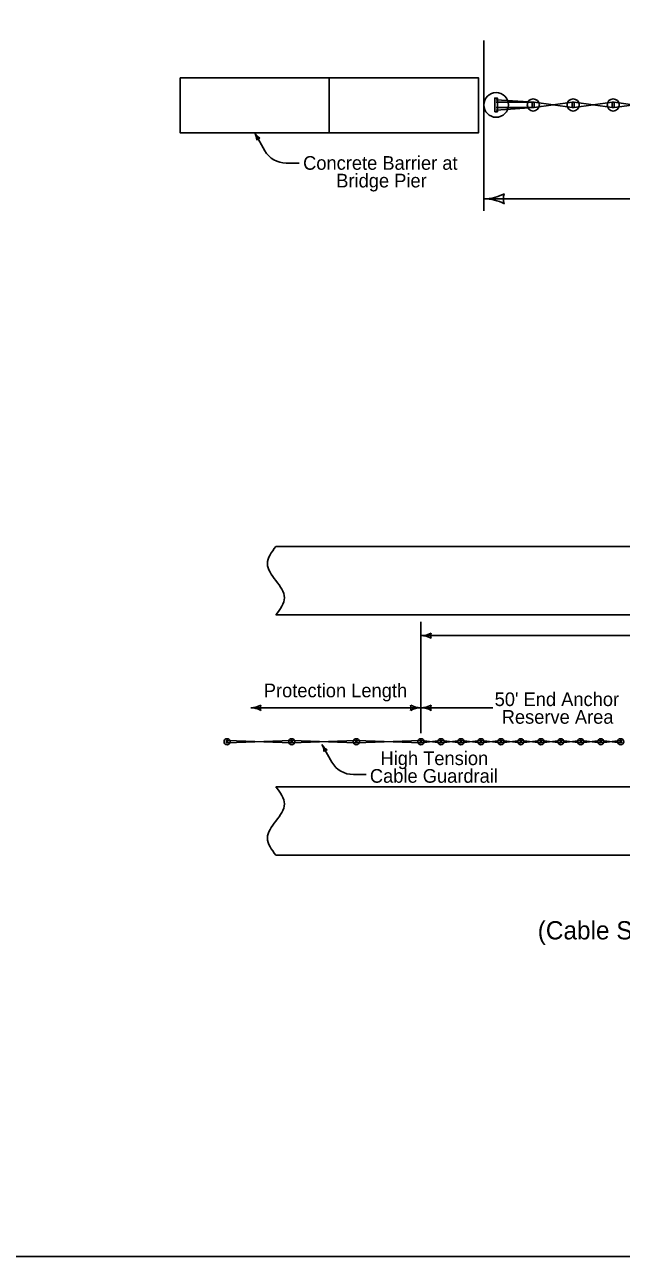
# Model space of a CAD drawing. Extents: x 10133 to 81668, y 7924 to 11018.
# Drawn here: x 22568 to 23092, y 7924 to 9005 of the extents above; entities that cross this region are included whole.
import ezdxf

# ---------------------------------------------------------------- set-up
doc = ezdxf.new("R2010")
doc.units = 0
for name, color, linetype in [('dsnCellElements', 7, 'Continuous'), ('DsnShtRevisedText', 7, 'Continuous'), ('dsnStdDimension', 7, 'Continuous'), ('Level 8', 7, 'Continuous'), ('SheetBorder', 7, 'Continuous')]:
    doc.layers.add(name, color=color, linetype=linetype)

msp = doc.modelspace()

# ---------------------------------------------------------------- linework, layer by layer
at = {"layer": 'dsnCellElements'}
for p, q in [((22981.8, 8939.2), (23015.3, 8936.9)), ((22981.8, 8936.9), (23013.5, 8936.9)), ((22981.8, 8932.4), (23013.5, 8932.4)), ((22981.8, 8930), (23015.3, 8932.4)), ((23015.3, 8936.9), (23048.5, 8932.4)), ((23015.3, 8932.4), (23048.5, 8936.9)), ((23050.4, 8936.9), (23083.6, 8932.4)), ((23050.4, 8932.4), (23083.6, 8936.9)), ((23085.5, 8936.9), (23118.7, 8932.4)), ((23085.5, 8932.4), (23118.7, 8936.9)), ((22801.9, 8376.8), (22746.1, 8374.6)), ((22801.9, 8374.6), (22746.1, 8376.8)), ((22858.6, 8376.8), (22802.9, 8374.6)), ((22858.6, 8374.6), (22802.9, 8376.8)), ((22915.3, 8376.8), (22859.6, 8374.6)), ((22915.3, 8374.6), (22859.6, 8376.8)), ((22932.9, 8376.8), (22916.3, 8374.6)), ((22932.9, 8374.6), (22916.3, 8376.8)), ((22950.4, 8376.8), (22933.8, 8374.6)), ((22950.4, 8374.6), (22933.8, 8376.8)), ((22968, 8376.8), (22951.3, 8374.6)), ((22968, 8374.6), (22951.3, 8376.8)), ((22985.5, 8376.8), (22968.9, 8374.6)), ((22985.5, 8374.6), (22968.9, 8376.8)), ((23003.1, 8376.8), (22986.4, 8374.6)), ((23003.1, 8374.6), (22986.4, 8376.8)), ((23020.6, 8376.8), (23004, 8374.6)), ((23020.6, 8374.6), (23004, 8376.8)), ((23038.2, 8376.8), (23021.5, 8374.6)), ((23038.2, 8374.6), (23021.5, 8376.8)), ((23055.7, 8374.6), (23039.1, 8376.8)), ((23055.7, 8376.8), (23039.1, 8374.6)), ((23073.2, 8376.8), (23056.6, 8374.6)), ((23073.2, 8374.6), (23056.6, 8376.8)), ((23090.8, 8376.8), (23074.2, 8374.6)), ((23090.8, 8374.6), (23074.2, 8376.8))]:
    msp.add_line(p, q, dxfattribs=at)
for points in [[(22980.6, 8928.6), (22980.6, 8940.6), (22983, 8940.6), (22983, 8928.6)], [(23013.5, 8932.4), (23013.5, 8936.9), (23015.3, 8936.9), (23015.3, 8932.4)], [(23048.5, 8932.4), (23048.5, 8936.9), (23050.4, 8936.9), (23050.4, 8932.4)], [(23083.7, 8932.4), (23083.7, 8936.9), (23085.5, 8936.9), (23085.5, 8932.4)], [(22746.1, 8374.6), (22746.1, 8376.8), (22745.2, 8376.8), (22745.2, 8374.6)], [(22802.9, 8374.6), (22802.9, 8376.8), (22801.9, 8376.8), (22801.9, 8374.6)], [(22802.9, 8374.6), (22802.9, 8376.8), (22801.9, 8376.8), (22801.9, 8374.6)], [(22859.6, 8374.6), (22859.6, 8376.8), (22858.6, 8376.8), (22858.6, 8374.6)], [(22859.6, 8374.6), (22859.6, 8376.8), (22858.6, 8376.8), (22858.6, 8374.6)], [(22916.3, 8374.6), (22916.3, 8376.8), (22915.3, 8376.8), (22915.3, 8374.6)], [(22916.3, 8374.6), (22916.3, 8376.8), (22915.3, 8376.8), (22915.3, 8374.6)], [(22933.8, 8374.6), (22933.8, 8376.8), (22932.9, 8376.8), (22932.9, 8374.6)], [(22951.3, 8374.6), (22951.3, 8376.8), (22950.4, 8376.8), (22950.4, 8374.6)], [(22968.9, 8374.6), (22968.9, 8376.8), (22968, 8376.8), (22968, 8374.6)], [(22986.4, 8374.6), (22986.4, 8376.8), (22985.5, 8376.8), (22985.5, 8374.6)], [(23004, 8374.6), (23004, 8376.8), (23003.1, 8376.8), (23003.1, 8374.6)], [(23021.5, 8374.6), (23021.5, 8376.8), (23020.6, 8376.8), (23020.6, 8374.6)], [(23039.1, 8374.6), (23039.1, 8376.8), (23038.2, 8376.8), (23038.2, 8374.6)], [(23056.6, 8374.6), (23056.6, 8376.8), (23055.7, 8376.8), (23055.7, 8374.6)], [(23074.2, 8374.6), (23074.2, 8376.8), (23073.2, 8376.8), (23073.2, 8374.6)], [(23091.7, 8374.6), (23091.7, 8376.8), (23090.8, 8376.8), (23090.8, 8374.6)]]:
    msp.add_lwpolyline(points, close=True, dxfattribs=at)
for centre, radius in [((22981.8, 8934.6), 10.8), ((23014.4, 8934.6), 5.32), ((23049.4, 8934.6), 5.32), ((23084.6, 8934.6), 5.32), ((22745.7, 8375.7), 2.66), ((22802.4, 8375.7), 2.66), ((22802.4, 8375.7), 2.66), ((22859.1, 8375.7), 2.66), ((22859.1, 8375.7), 2.66), ((22915.8, 8375.7), 2.66), ((22915.8, 8375.7), 2.66), ((22933.4, 8375.7), 2.66), ((22950.9, 8375.7), 2.66), ((22968.4, 8375.7), 2.66), ((22986, 8375.7), 2.66), ((23003.5, 8375.7), 2.66), ((23021.1, 8375.7), 2.66), ((23038.6, 8375.7), 2.66), ((23056.1, 8375.7), 2.66), ((23073.7, 8375.7), 2.66), ((23091.2, 8375.7), 2.66)]:
    msp.add_circle(centre, radius, dxfattribs=at)
at = {"layer": 'DsnShtRevisedText'}
for p, q in [((22971, 8841.7), (22971, 8991.2)), ((22778.8, 8894.4), (22769.9, 8910)), ((22797.6, 8883.6), (22808.8, 8883.6)), ((22971, 8852.2), (23201.1, 8852.2)), ((22915.8, 8383.2), (22915.8, 8480.8)), ((23207.3, 8468.8), (22915.8, 8468.8)), ((22892.8, 8405.5), (22766.4, 8405.5)), ((22915.8, 8405.5), (22892.8, 8405.5)), ((22979, 8405.5), (22915.8, 8405.5)), ((22837.7, 8357.7), (22828.9, 8373.3)), ((22856.5, 8346.9), (22867.8, 8346.9))]:
    msp.add_line(p, q, dxfattribs=at)
for centre, radius, start, end in [((22758.2, 8903.2), 13.6, 2.1589, 30.2314), ((22781.7, 8916.9), 13.6, 210.2314, 238.3038), ((22775.6, 8900.2), 5.25, 102.498, 137.9647), ((22797.6, 8905.3), 21.8, 210.2243, 270), ((22971, 8890.5), 38.3, 270, 298.0725), ((23003, 8852.2), 14.8, 162.2666, 197.7334), ((22971, 8814), 38.3, 61.9275, 90), ((22915.8, 8487.9), 19.1, 270, 298.0725), ((22915.8, 8449.7), 19.1, 61.9275, 90), ((22931.8, 8468.8), 7.39, 162.2666, 197.7334), ((22766.4, 8424.7), 19.1, 270, 298.0725), ((22766.4, 8386.4), 19.1, 61.9275, 90), ((22782.4, 8405.5), 7.39, 162.2666, 197.7334), ((22899.7, 8405.5), 7.39, 342.2666, 17.7333), ((22915.8, 8424.7), 19.1, 241.9275, 270), ((22915.8, 8386.4), 19.1, 90, 118.0725), ((22915.8, 8424.7), 19.1, 270, 298.0725), ((22915.8, 8386.4), 19.1, 61.9275, 90), ((22931.8, 8405.5), 7.39, 162.2666, 197.7334), ((22817.1, 8366.5), 13.6, 2.1589, 30.2314), ((22840.6, 8380.2), 13.6, 210.2314, 238.3038), ((22834.6, 8363.5), 5.25, 102.498, 137.9647), ((22856.5, 8368.7), 21.8, 210.2243, 270)]:
    msp.add_arc(centre, radius, start, end, dxfattribs=at)
at = {"layer": 'dsnStdDimension'}
for p, q in [((22788.5, 8547.1), (23664.1, 8547.1)), ((22788.5, 8487.1), (23664.1, 8487.1)), ((22788.5, 8336.1), (23664.1, 8336.1)), ((22788.5, 8276.1), (23664.1, 8276.1))]:
    msp.add_line(p, q, dxfattribs=at)
for points in [[(22704.5, 8958.5), (22835.4, 8958.5), (22835.4, 8910), (22704.5, 8910)], [(22835.4, 8958.5), (22966.3, 8958.5), (22966.3, 8910), (22835.4, 8910)]]:
    msp.add_lwpolyline(points, close=True, dxfattribs=at)
for points in [[(22788.5, 8487.1), (22796, 8502.1), (22788.5, 8517.1), (22781, 8532.1), (22788.5, 8547.1)], [(22788.5, 8336.1), (22796, 8321.1), (22788.5, 8306.1), (22781, 8291.1), (22788.5, 8276.1)]]:
    msp.add_spline(points, degree=3, dxfattribs=at)
at = {"layer": 'SheetBorder'}
msp.add_lwpolyline([(20932.5, 9944), (24067.5, 9944), (24067.5, 7924), (20932.5, 7924)], close=True, dxfattribs=at)

# ---------------------------------------------------------------- texts
at = {"layer": 'DsnShtRevisedText'}
for s, p in [('Concrete Barrier at ', (22812.4, 8877.7)), ('Bridge Pier', (22841.5, 8862.2)), ('Protection Length', (22777.9, 8414.7)), ("50' End Anchor", (22980.5, 8407)), ('Reserve Area', (22986.7, 8391.5)), ('High Tension', (22880.3, 8355.2)), ('Cable Guardrail', (22871, 8339.7))]:
    msp.add_text(s, height=12, dxfattribs=at).set_placement(p)
at = {"layer": 'Level 8'}
msp.add_text('(Cable Switches from Near Side to Far Side)', height=16, dxfattribs=at).set_placement((23018.3, 8202.2))

doc.saveas('drawing.dxf')
